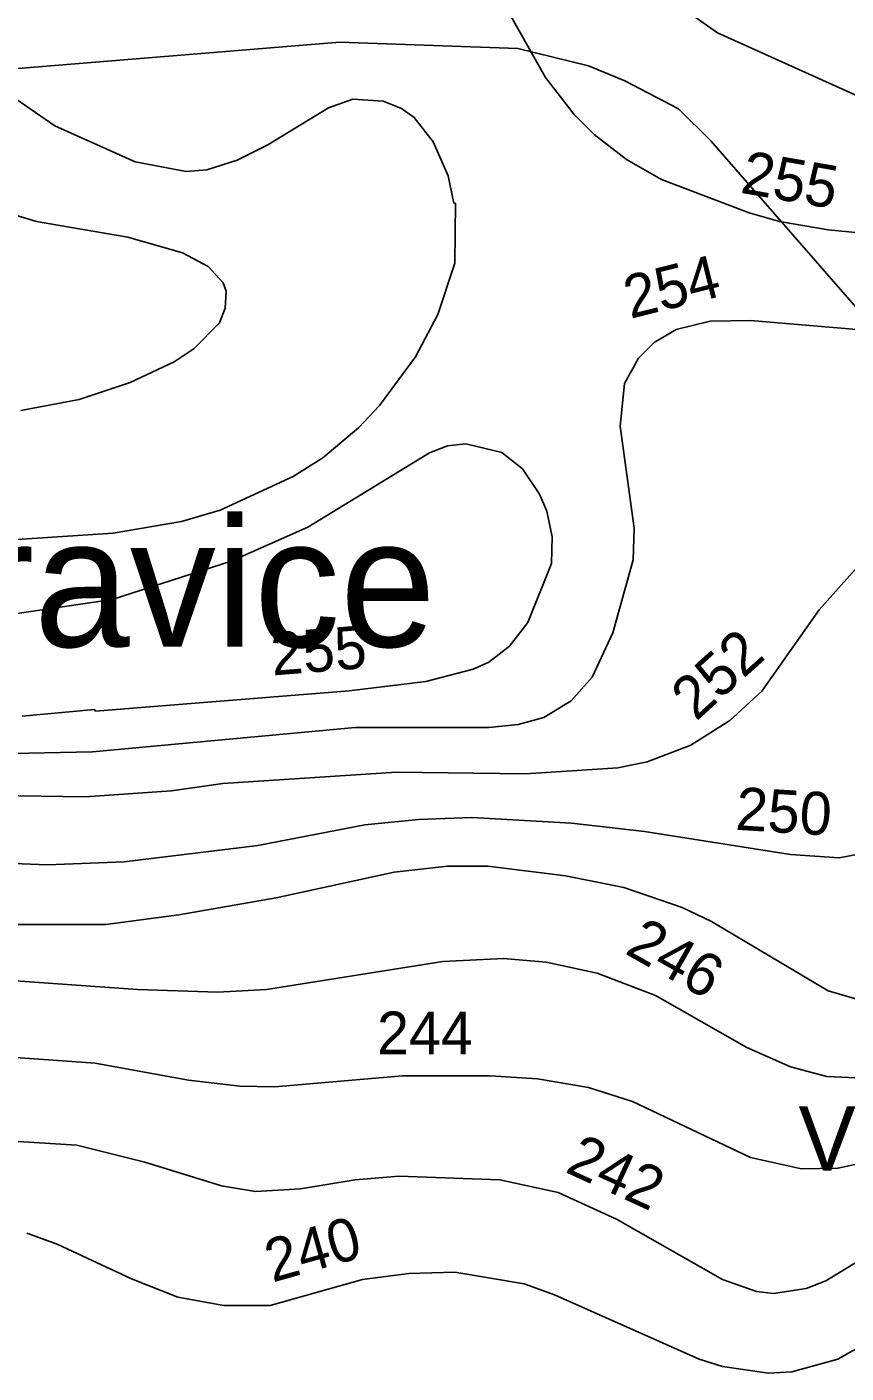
# Model space of a CAD drawing. Extents: x -662500 to -655523, y -1056000 to -1049993.
# Drawn here: x -661263.9 to -661073, y -1051978.8 to -1051664.9 of the extents above; entities that cross this region are included whole.
import ezdxf

# ---------------------------------------------------------------- set-up
doc = ezdxf.new("R2010")
doc.units = 0
for name, color, linetype in [('58', 7, 'Continuous'), ('Vrstva 24', 7, 'Continuous'), ('Vrstva 61', 7, 'Continuous'), ('Vrstva 7', 7, 'Continuous')]:
    doc.layers.add(name, color=color, linetype=linetype)

msp = doc.modelspace()

# ---------------------------------------------------------------- linework, layer by layer
at = {"layer": 'Vrstva 24'}
msp.add_lwpolyline([(-661325.5, -1051678.5), (-661276.5, -1051675.5), (-661191, -1051668.5), (-661149.5, -1051670), (-661133, -1051674), (-661124.5, -1051677.5), (-661112, -1051684), (-661104.5, -1051691.5), (-661026, -1051781.5), (-661005, -1051798), (-660983, -1051806.5), (-660947.48, -1051815.82)], dxfattribs=at)
at = {"layer": 'Vrstva 7'}
for p, q in [((-661155.78, -1051654.02), (-661143.03, -1051676.7)), ((-661102.92, -1051666.35), (-661115.96, -1051657.14)), ((-661058.14, -1051686.48), (-661102.92, -1051666.35)), ((-661257.4, -1051688.03), (-661276.53, -1051674.85)), ((-661143.03, -1051676.7), (-661136.37, -1051685.34)), ((-661193.62, -1051683.78), (-661207.79, -1051692.43)), ((-661187.95, -1051681.8), (-661193.62, -1051683.78)), ((-661180.87, -1051682.23), (-661187.95, -1051681.8)), ((-661176.62, -1051683.93), (-661180.87, -1051682.23)), ((-661173.64, -1051686.05), (-661176.62, -1051683.93)), ((-661238.69, -1051696.4), (-661257.4, -1051688.03)), ((-661169.25, -1051691.72), (-661173.64, -1051686.05)), ((-661136.37, -1051685.34), (-661131.69, -1051690.02)), ((-661131.69, -1051690.02), (-661124.18, -1051695.83)), ((-661207.79, -1051692.43), (-661214.88, -1051695.97)), ((-661165.7, -1051699.66), (-661169.25, -1051691.72)), ((-661226.78, -1051698.66), (-661238.69, -1051696.4)), ((-661214.88, -1051695.97), (-661221.97, -1051698.24)), ((-661124.18, -1051695.83), (-661115.96, -1051700.51)), ((-661221.97, -1051698.24), (-661226.78, -1051698.66)), ((-661164.43, -1051706.03), (-661165.7, -1051699.66)), ((-661115.96, -1051700.51), (-661095.55, -1051708.3)), ((-661164, -1051706.03), (-661164.43, -1051706.03)), ((-661164.15, -1051720.06), (-661164, -1051706.03)), ((-661261.65, -1051710.28), (-661270.15, -1051707.73)), ((-661095.55, -1051708.3), (-661088.47, -1051710.28)), ((-661240.39, -1051713.97), (-661261.65, -1051710.28)), ((-661088.47, -1051710.28), (-661077.13, -1051712.27)), ((-661077.13, -1051712.27), (-661065.23, -1051713.4)), ((-661227.63, -1051717.65), (-661240.39, -1051713.97)), ((-661221.68, -1051720.77), (-661227.63, -1051717.65)), ((-661218.14, -1051724.6), (-661221.68, -1051720.77)), ((-661168.11, -1051731.97), (-661164.15, -1051720.06)), ((-661217.43, -1051726.58), (-661218.14, -1051724.6)), ((-661217.71, -1051730.55), (-661217.43, -1051726.58)), ((-661218.99, -1051733.95), (-661217.71, -1051730.55)), ((-661173.36, -1051741.89), (-661168.11, -1051731.97)), ((-661224.94, -1051739.9), (-661218.99, -1051733.95)), ((-661104.62, -1051733.53), (-661112.56, -1051735.51)), ((-661095.27, -1051733.38), (-661104.62, -1051733.53)), ((-661055.59, -1051736.78), (-661095.27, -1051733.38)), ((-661112.56, -1051735.51), (-661117.66, -1051738.49)), ((-661229.62, -1051743.02), (-661224.94, -1051739.9)), ((-661117.66, -1051738.49), (-661121.35, -1051742.17)), ((-661239.82, -1051747.84), (-661229.62, -1051743.02)), ((-661181.72, -1051753.22), (-661173.36, -1051741.89)), ((-661121.35, -1051742.17), (-661124.61, -1051748.12)), ((-661251.73, -1051751.81), (-661239.82, -1051747.84)), ((-661124.61, -1051748.12), (-661125.6, -1051758.04)), ((-661265.33, -1051754.36), (-661251.73, -1051751.81)), ((-661186.54, -1051758.33), (-661181.72, -1051753.22)), ((-661194.9, -1051765.41), (-661186.54, -1051758.33)), ((-661125.6, -1051758.04), (-661122.34, -1051781.85)), ((-661165.85, -1051762.58), (-661170.1, -1051764.28)), ((-661161.59, -1051762.15), (-661165.85, -1051762.58)), ((-661153.23, -1051764.14), (-661161.59, -1051762.15)), ((-661201.84, -1051769.8), (-661194.9, -1051765.41)), ((-661170.1, -1051764.28), (-661198.44, -1051781.57)), ((-661148.42, -1051767.96), (-661153.23, -1051764.14)), ((-661144.45, -1051773.92), (-661148.42, -1051767.96)), ((-661218.85, -1051777.6), (-661201.84, -1051769.8)), ((-661142.75, -1051777.88), (-661144.45, -1051773.92)), ((-661227.92, -1051780.29), (-661218.85, -1051777.6)), ((-661141.47, -1051783.84), (-661142.75, -1051777.88)), ((-661243.79, -1051782.99), (-661227.92, -1051780.29)), ((-661198.44, -1051781.57), (-661216.3, -1051789.5)), ((-661122.34, -1051781.85), (-661122.62, -1051789.22)), ((-661287.16, -1051785.82), (-661243.79, -1051782.99)), ((-661141.61, -1051790.07), (-661141.47, -1051783.84)), ((-661216.3, -1051789.5), (-661244.07, -1051798.43)), ((-661147.14, -1051803.82), (-661141.61, -1051790.07)), ((-661122.62, -1051789.22), (-661127.3, -1051806.23)), ((-661070.19, -1051790.78), (-661079.26, -1051800.84)), ((-661244.07, -1051798.43), (-661271.57, -1051802.54)), ((-661079.26, -1051800.84), (-661092.58, -1051819.83)), ((-661151.39, -1051809.34), (-661147.14, -1051803.82)), ((-661127.3, -1051806.23), (-661132.12, -1051816.57)), ((-661156.21, -1051813.03), (-661151.39, -1051809.34)), ((-661159.89, -1051814.73), (-661156.21, -1051813.03)), ((-661170.95, -1051817.56), (-661159.89, -1051814.73)), ((-661132.12, -1051816.57), (-661137.08, -1051822.1)), ((-661247.9, -1051824.51), (-661188.83, -1051819.77)), ((-661188.83, -1051819.77), (-661170.95, -1051817.56)), ((-661092.58, -1051819.83), (-661100.09, -1051826.63)), ((-661137.08, -1051822.1), (-661143.45, -1051825.93)), ((-661265.05, -1051825.64), (-661248.13, -1051824.07)), ((-661248.13, -1051824.07), (-661247.9, -1051824.51)), ((-661143.45, -1051825.93), (-661149.41, -1051827.62)), ((-661187.39, -1051828.33), (-661248.61, -1051834)), ((-661156.21, -1051828.33), (-661187.39, -1051828.33)), ((-661149.41, -1051827.62), (-661156.21, -1051828.33)), ((-661100.09, -1051826.63), (-661109.16, -1051832.44)), ((-661109.16, -1051832.44), (-661119.36, -1051836.27)), ((-661248.61, -1051834), (-661271, -1051834.43)), ((-661177.75, -1051838.68), (-661218.28, -1051841.37)), ((-661147.71, -1051839.1), (-661177.75, -1051838.68)), ((-661126.17, -1051837.69), (-661147.71, -1051839.1)), ((-661119.36, -1051836.27), (-661126.17, -1051837.69)), ((-661218.28, -1051841.37), (-661230.19, -1051843.07)), ((-661250.31, -1051844.49), (-661278.08, -1051844.06)), ((-661230.19, -1051843.07), (-661250.31, -1051844.49)), ((-661185.12, -1051851.01), (-661210.06, -1051855.83)), ((-661172.65, -1051849.73), (-661185.12, -1051851.01)), ((-661160.18, -1051849.31), (-661172.65, -1051849.73)), ((-661136.94, -1051850.58), (-661160.18, -1051849.31)), ((-661119.93, -1051852.57), (-661136.94, -1051850.58)), ((-661085.92, -1051857.95), (-661119.93, -1051852.57)), ((-661210.06, -1051855.83), (-661241.24, -1051859.65)), ((-661259.09, -1051860.36), (-661276.1, -1051859.65)), ((-661241.24, -1051859.65), (-661259.09, -1051860.36)), ((-661178.32, -1051862.06), (-661165.85, -1051860.65)), ((-661178.32, -1051862.06), (-661165.85, -1051860.65)), ((-661165.85, -1051860.65), (-661156.49, -1051860.65)), ((-661165.85, -1051860.65), (-661156.49, -1051860.65)), ((-661156.49, -1051860.65), (-661138.35, -1051862.91)), ((-661156.49, -1051860.65), (-661138.35, -1051862.91)), ((-661074.58, -1051858.66), (-661085.92, -1051857.95)), ((-661069.2, -1051857.67), (-661074.58, -1051858.66)), ((-661205.81, -1051868.02), (-661178.32, -1051862.06)), ((-661205.81, -1051868.02), (-661178.32, -1051862.06)), ((-661138.35, -1051862.91), (-661124.75, -1051865.6)), ((-661138.35, -1051862.91), (-661124.75, -1051865.6)), ((-661124.75, -1051865.6), (-661111.14, -1051870.28)), ((-661124.75, -1051865.6), (-661111.14, -1051870.28)), ((-661228.48, -1051871.98), (-661205.81, -1051868.02)), ((-661228.48, -1051871.98), (-661205.81, -1051868.02)), ((-661245.49, -1051874.25), (-661228.48, -1051871.98)), ((-661245.49, -1051874.25), (-661228.48, -1051871.98)), ((-661111.14, -1051870.28), (-661104.34, -1051873.54)), ((-661111.14, -1051870.28), (-661104.34, -1051873.54)), ((-661269.87, -1051874.25), (-661245.49, -1051874.25)), ((-661269.87, -1051874.25), (-661245.49, -1051874.25)), ((-661104.34, -1051873.54), (-661077.13, -1051889.7)), ((-661104.34, -1051873.54), (-661077.13, -1051889.7)), ((-661166.98, -1051882.9), (-661152.81, -1051882.19)), ((-661166.98, -1051882.9), (-661152.81, -1051882.19)), ((-661152.81, -1051882.19), (-661142.89, -1051883.04)), ((-661152.81, -1051882.19), (-661142.89, -1051883.04)), ((-661299.34, -1051885.02), (-661238.12, -1051889.41)), ((-661299.34, -1051885.02), (-661238.12, -1051889.41)), ((-661208.08, -1051889.41), (-661166.98, -1051882.9)), ((-661208.08, -1051889.41), (-661166.98, -1051882.9)), ((-661142.89, -1051883.04), (-661130.98, -1051885.59)), ((-661142.89, -1051883.04), (-661130.98, -1051885.59)), ((-661130.98, -1051885.59), (-661117.38, -1051890.83)), ((-661130.98, -1051885.59), (-661117.38, -1051890.83)), ((-661238.12, -1051889.41), (-661219.42, -1051889.98)), ((-661238.12, -1051889.41), (-661219.42, -1051889.98)), ((-661219.42, -1051889.98), (-661208.08, -1051889.41)), ((-661219.42, -1051889.98), (-661208.08, -1051889.41)), ((-661117.38, -1051890.83), (-661096.12, -1051902.88)), ((-661117.38, -1051890.83), (-661096.12, -1051902.88)), ((-661077.13, -1051889.7), (-661066.93, -1051892.67)), ((-661077.13, -1051889.7), (-661066.93, -1051892.67)), ((-661248.04, -1051906.56), (-661299.34, -1051902.88)), ((-661096.12, -1051902.88), (-661085.92, -1051907.41)), ((-661096.12, -1051902.88), (-661085.92, -1051907.41)), ((-661226.22, -1051910.53), (-661248.04, -1051906.56)), ((-661085.92, -1051907.41), (-661077.42, -1051909.68)), ((-661085.92, -1051907.41), (-661077.42, -1051909.68)), ((-661214.31, -1051911.95), (-661226.22, -1051910.53)), ((-661176.33, -1051909.54), (-661206.09, -1051912.09)), ((-661155.93, -1051909.54), (-661176.33, -1051909.54)), ((-661144.87, -1051910.25), (-661155.93, -1051909.54)), ((-661132.97, -1051912.23), (-661144.87, -1051910.25)), ((-661077.42, -1051909.68), (-661070.61, -1051909.96)), ((-661077.42, -1051909.68), (-661070.61, -1051909.96)), ((-661206.09, -1051912.09), (-661214.31, -1051911.95)), ((-661122.76, -1051915.49), (-661132.97, -1051912.23)), ((-661095.27, -1051928.53), (-661122.76, -1051915.49)), ((-661252.29, -1051925.69), (-661291.97, -1051923.28)), ((-661236.42, -1051929.66), (-661252.29, -1051925.69)), ((-661218.56, -1051935.19), (-661236.42, -1051929.66)), ((-661083.37, -1051931.22), (-661095.27, -1051928.53)), ((-661065.79, -1051929.09), (-661074.86, -1051931.08)), ((-661074.86, -1051931.08), (-661083.37, -1051931.22)), ((-661210.63, -1051936.46), (-661218.56, -1051935.19)), ((-661200.14, -1051935.9), (-661210.63, -1051936.46)), ((-661187.39, -1051933.77), (-661200.14, -1051935.9)), ((-661177.18, -1051932.92), (-661187.39, -1051933.77)), ((-661153.66, -1051933.77), (-661177.18, -1051932.92)), ((-661140.05, -1051936.75), (-661153.66, -1051933.77)), ((-661126.45, -1051942.98), (-661140.05, -1051936.75)), ((-661101.79, -1051957.01), (-661126.45, -1051942.98)), ((-661263.91, -1051946.24), (-661256.83, -1051948.79)), ((-661256.83, -1051948.79), (-661239.54, -1051956.87)), ((-661069.48, -1051952.34), (-661077.7, -1051957.3)), ((-661239.54, -1051956.87), (-661228.77, -1051961.12)), ((-661207.23, -1051963.11), (-661185.69, -1051957.01)), ((-661185.69, -1051957.01), (-661174.92, -1051955.6)), ((-661174.92, -1051955.6), (-661164.15, -1051955.31)), ((-661164.15, -1051955.31), (-661147.99, -1051958.01)), ((-661147.99, -1051958.01), (-661140.9, -1051960.56)), ((-661093.85, -1051959.85), (-661101.79, -1051957.01)), ((-661077.7, -1051957.3), (-661082.23, -1051959.14)), ((-661228.77, -1051961.12), (-661218, -1051963.11)), ((-661140.9, -1051960.56), (-661107.18, -1051975.58)), ((-661089.89, -1051960.27), (-661093.85, -1051959.85)), ((-661082.23, -1051959.14), (-661089.89, -1051960.27)), ((-661218, -1051963.11), (-661207.23, -1051963.11)), ((-661074.86, -1051975.58), (-661069.48, -1051972.6)), ((-661107.18, -1051975.58), (-661101.79, -1051977.28)), ((-661085.63, -1051978.55), (-661074.86, -1051975.58)), ((-661101.79, -1051977.28), (-661091.02, -1051978.84)), ((-661091.02, -1051978.84), (-661085.63, -1051978.55))]:
    msp.add_line(p, q, dxfattribs=at)

# ---------------------------------------------------------------- texts
at = {"layer": '58'}
msp.add_text('k.ú. Žáravice', height=30, dxfattribs=at).set_placement((-661398.23, -1051809.48))
at = {"layer": 'Vrstva 61'}
msp.add_text('V2', height=15, dxfattribs=at).set_placement((-661084.06, -1051931.62))
at = {"layer": 'Vrstva 7'}
for s, rotation, p in [('255', 350.0745, (-661097.84, -1051703.57)), ('254', 14.0362, (-661123.28, -1051733.03)), ('255', 4.5876, (-661206.66, -1051816.18)), ('252', 42.1683, (-661107.95, -1051827)), ('250', 356.4218, (-661098.89, -1051852.13)), ('246', 330.4616, (-661124.81, -1051880.87)), ('242', 335.3735, (-661138.74, -1051931.85)), ('240', 15.7963, (-661206.7, -1051957.76))]:
    msp.add_text(s, height=10, rotation=rotation, dxfattribs=at).set_placement(p)
msp.add_text('244', height=10, dxfattribs=at).set_placement((-661182.29, -1051904.54))

doc.saveas('drawing.dxf')
